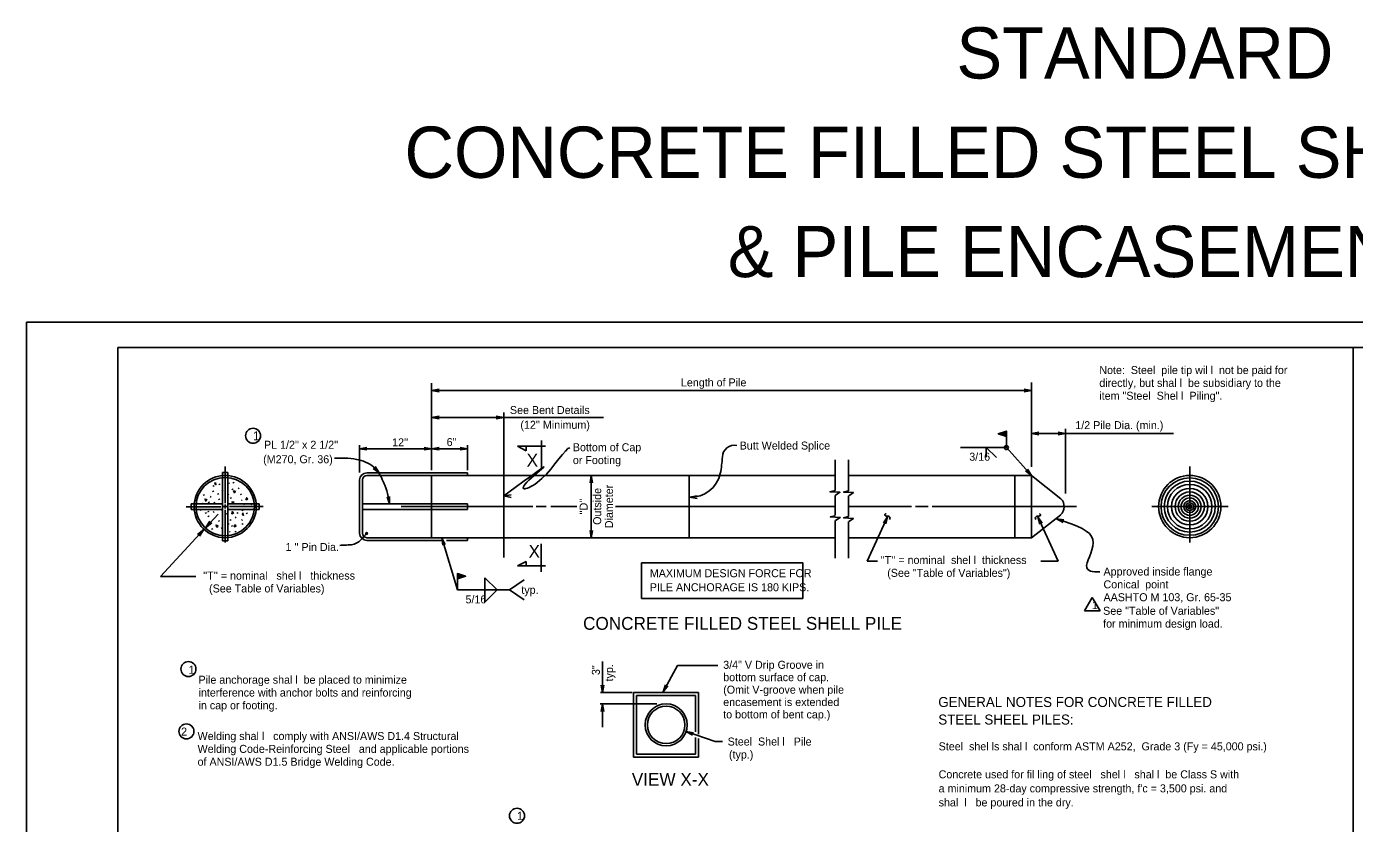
# Model space of a CAD drawing. Extents: x 1053 to 1311, y 5085 to 5337.
# Drawn here: x 1053.3 to 1163.9, y 5270.9 to 5337.3 of the extents above; entities that cross this region are included whole.
import ezdxf

# ---------------------------------------------------------------- set-up
doc = ezdxf.new("R2010")
doc.units = 0
for name, color, linetype in [('1', 7, 'Continuous'), ('2', 7, 'Continuous'), ('5', 7, 'Continuous'), ('7', 7, 'Continuous'), ('9', 7, 'Continuous'), ('B_Dimension', 7, 'Continuous'), ('B_No_Plot', 7, 'Continuous')]:
    doc.layers.add(name, color=color, linetype=linetype)

msp = doc.modelspace()

# ---------------------------------------------------------------- linework, layer by layer
at = {"layer": '1'}
for p, q in [((1060.92, 5310.54), (1229.53, 5310.54)), ((1060.92, 5200.97), (1060.92, 5310.54)), ((1087.04, 5307.57), (1087.04, 5300.32)), ((1087.04, 5306.96), (1137, 5306.96)), ((1137, 5307.62), (1137, 5300.59)), ((1093.04, 5304.71), (1087.04, 5304.71)), ((1101.34, 5304.71), (1093.04, 5304.71)), ((1134.9, 5303.58), (1134.22, 5303.36)), ((1134.9, 5303.13), (1134.22, 5303.36)), ((1134.26, 5303.34), (1134.24, 5303.36)), ((1134.25, 5303.34), (1134.29, 5303.38)), ((1134.38, 5303.3), (1134.3, 5303.38)), ((1134.31, 5303.32), (1134.4, 5303.42)), ((1134.49, 5303.27), (1134.36, 5303.4)), ((1134.37, 5303.31), (1134.52, 5303.45)), ((1134.61, 5303.23), (1134.42, 5303.42)), ((1134.43, 5303.29), (1134.63, 5303.49)), ((1134.72, 5303.19), (1134.47, 5303.44)), ((1134.49, 5303.27), (1134.75, 5303.53)), ((1134.84, 5303.15), (1134.53, 5303.46)), ((1134.55, 5303.25), (1134.86, 5303.57)), ((1134.9, 5303.17), (1134.59, 5303.48)), ((1134.61, 5303.23), (1134.9, 5303.52)), ((1134.9, 5303.25), (1134.65, 5303.5)), ((1134.66, 5303.21), (1134.9, 5303.45)), ((1134.9, 5303.32), (1134.71, 5303.52)), ((1134.72, 5303.19), (1134.9, 5303.37)), ((1134.9, 5303.4), (1134.77, 5303.53)), ((1134.9, 5303.48), (1134.83, 5303.55)), ((1134.9, 5303.56), (1134.89, 5303.57)), ((1134.9, 5302.21), (1134.9, 5303.58)), ((1139.82, 5303.39), (1137, 5303.39)), ((1139.82, 5303.77), (1139.82, 5298.38)), ((1148.83, 5303.39), (1139.82, 5303.39)), ((1081.04, 5302.4), (1081.04, 5300.12)), ((1090.04, 5302.4), (1090.04, 5300.32)), ((1096.52, 5302.31), (1094.2, 5302.31)), ((1094.92, 5302.31), (1094.92, 5301.94)), ((1096.18, 5302.79), (1096.18, 5300.47)), ((1134.9, 5302.21), (1131.08, 5302.21)), ((1133.23, 5302.21), (1133.23, 5301.41)), ((1134.07, 5301.38), (1133.23, 5302.21)), ((1134.78, 5303.17), (1134.9, 5303.29)), ((1134.84, 5303.15), (1134.9, 5303.21)), ((1134.9, 5303.13), (1134.9, 5303.14)), ((1134.9, 5302.21), (1137, 5299.88)), ((1087.04, 5302.11), (1081.04, 5302.11)), ((1090.04, 5302.11), (1087.04, 5302.11)), ((1120.65, 5301.18), (1120.65, 5298.64)), ((1121.76, 5301.18), (1121.76, 5298.61)), ((1070.08, 5300.13), (1069.62, 5300.13)), ((1069.62, 5300.13), (1069.62, 5294.45)), ((1069.85, 5300.62), (1069.85, 5297.58)), ((1070.08, 5294.45), (1070.08, 5300.13)), ((1090.04, 5300.1), (1081.64, 5300.1)), ((1090.04, 5300.1), (1090.04, 5299.88)), ((1150.17, 5300.63), (1150.17, 5297.59)), ((1068.85, 5299.04), (1068.91, 5298.97)), ((1069.34, 5299.19), (1069.39, 5299.11)), ((1070.15, 5299.28), (1070.21, 5299.21)), ((1070.52, 5299.32), (1070.57, 5299.24)), ((1081.04, 5295.07), (1081.04, 5299.51)), ((1081.27, 5295.07), (1081.27, 5299.51)), ((1087.04, 5299.88), (1081.64, 5299.88)), ((1087.04, 5294.7), (1087.04, 5299.88)), ((1087.04, 5299.88), (1120.65, 5299.88)), ((1100.33, 5299.88), (1100.33, 5294.7)), ((1108.49, 5294.7), (1108.49, 5299.88)), ((1121.76, 5299.88), (1137, 5299.88)), ((1135.6, 5294.7), (1135.6, 5299.88)), ((1137, 5294.7), (1137, 5299.88)), ((1137, 5299.88), (1139.44, 5297.95)), ((1068.05, 5298.3), (1068.1, 5298.22)), ((1068.61, 5298.14), (1068.67, 5298.07)), ((1068.82, 5298.59), (1068.87, 5298.51)), ((1069.23, 5298.37), (1069.29, 5298.3)), ((1069.33, 5297.94), (1069.38, 5297.86)), ((1069.6, 5298.69), (1069.65, 5298.61)), ((1070.08, 5298.33), (1070.13, 5298.25)), ((1070.29, 5298.04), (1070.35, 5297.96)), ((1070.42, 5298.77), (1070.48, 5298.7)), ((1070.94, 5298.85), (1071, 5298.77)), ((1071.14, 5298.35), (1071.19, 5298.27)), ((1071.2, 5297.86), (1071.26, 5297.79)), ((1108.51, 5298.07), (1109.16, 5298.19)), ((1108.51, 5298.07), (1109.16, 5297.96)), ((1120.65, 5298.21), (1120.65, 5296.57)), ((1121.76, 5298.18), (1121.76, 5296.47)), ((1066.61, 5297.28), (1069.49, 5297.28)), ((1067.01, 5297.52), (1067.01, 5297.06)), ((1067.01, 5297.52), (1069.62, 5297.52)), ((1067.01, 5297.06), (1069.62, 5297.06)), ((1067.8, 5297.05), (1067.85, 5296.97)), ((1067.97, 5297.58), (1068.03, 5297.51)), ((1068.2, 5296.79), (1068.26, 5296.71)), ((1068.42, 5296.92), (1068.47, 5296.84)), ((1068.45, 5297.69), (1068.51, 5297.61)), ((1068.86, 5296.87), (1068.92, 5296.79)), ((1068.92, 5297.66), (1068.97, 5297.58)), ((1069.57, 5297.04), (1069.62, 5296.96)), ((1069.71, 5297.29), (1070.02, 5297.29)), ((1069.85, 5297.46), (1069.85, 5297.14)), ((1069.85, 5297.02), (1069.85, 5294.3)), ((1069.96, 5296.73), (1070.01, 5296.65)), ((1070.08, 5297.52), (1072.69, 5297.52)), ((1070.08, 5297.06), (1072.69, 5297.06)), ((1070.13, 5297.08), (1070.18, 5297.01)), ((1070.21, 5297.29), (1073.01, 5297.29)), ((1070.85, 5296.79), (1070.9, 5296.71)), ((1071.27, 5297.03), (1071.32, 5296.95)), ((1071.42, 5297.52), (1071.47, 5297.44)), ((1071.63, 5296.77), (1071.68, 5296.69)), ((1072.02, 5297.53), (1072.07, 5297.45)), ((1072.69, 5297.06), (1072.69, 5297.52)), ((1081.04, 5297.4), (1081.04, 5297.17)), ((1090.04, 5297.52), (1081.27, 5297.52)), ((1090.04, 5297.06), (1081.27, 5297.06)), ((1084.5, 5297.29), (1095.46, 5297.29)), ((1090.04, 5297.52), (1090.04, 5297.06)), ((1095.74, 5297.29), (1096.59, 5297.29)), ((1096.97, 5297.29), (1099.14, 5297.29)), ((1102.36, 5297.29), (1120.65, 5297.29)), ((1121.76, 5297.29), (1126.99, 5297.29)), ((1127.33, 5297.29), (1128.39, 5297.29)), ((1128.73, 5297.29), (1140.73, 5297.29)), ((1147.01, 5297.29), (1150.17, 5297.29)), ((1150, 5297.29), (1150.33, 5297.29)), ((1150.17, 5297.46), (1150.17, 5297.14)), ((1150.17, 5297.03), (1150.17, 5294.31)), ((1150.51, 5297.29), (1153.38, 5297.29)), ((1069.27, 5296.66), (1068.22, 5295.53)), ((1068.22, 5295.53), (1068.58, 5296.09)), ((1068.22, 5295.53), (1068.75, 5295.93)), ((1068.43, 5296.53), (1068.48, 5296.45)), ((1069.31, 5296.13), (1069.36, 5296.05)), ((1070.11, 5295.87), (1070.16, 5295.79)), ((1070.27, 5296.21), (1070.33, 5296.13)), ((1070.39, 5295.71), (1070.44, 5295.63)), ((1070.69, 5296.42), (1070.75, 5296.35)), ((1071.22, 5296.22), (1071.28, 5296.14)), ((1071.27, 5295.87), (1071.32, 5295.79)), ((1120.65, 5296.14), (1120.65, 5292.99)), ((1121.76, 5296.04), (1121.76, 5292.99)), ((1125.01, 5296.44), (1123.31, 5292.74)), ((1139.43, 5296.61), (1137, 5294.7)), ((1137.52, 5296.44), (1139.22, 5292.74)), ((1068.08, 5295.38), (1064.46, 5291.48)), ((1068.08, 5295.38), (1067.55, 5294.98)), ((1068.08, 5295.38), (1067.72, 5294.83)), ((1068.73, 5295.47), (1068.79, 5295.39)), ((1069.53, 5295.54), (1069.59, 5295.47)), ((1070.2, 5295.23), (1070.25, 5295.15)), ((1070.68, 5295.24), (1070.74, 5295.17)), ((1087.04, 5294.7), (1081.64, 5294.7)), ((1087.82, 5294.47), (1081.64, 5294.47)), ((1087.04, 5294.7), (1120.65, 5294.7)), ((1090.04, 5294.47), (1088.27, 5294.47)), ((1090.04, 5294.47), (1090.04, 5294.7)), ((1121.76, 5294.7), (1137, 5294.7)), ((1069.62, 5294.45), (1070.08, 5294.45)), ((1096.17, 5291.87), (1096.17, 5294.19)), ((1096.51, 5292.35), (1094.19, 5292.35)), ((1094.91, 5292.35), (1094.91, 5292.72)), ((1123.31, 5292.74), (1124.18, 5292.74)), ((1139.22, 5292.74), (1137.77, 5292.74)), ((1064.46, 5291.48), (1067.4, 5291.48)), ((1089.18, 5290.35), (1089.18, 5291.71)), ((1089.18, 5291.71), (1089.86, 5291.49)), ((1089.18, 5291.69), (1089.19, 5291.71)), ((1089.18, 5291.61), (1089.25, 5291.69)), ((1089.18, 5291.54), (1089.31, 5291.67)), ((1089.47, 5291.36), (1089.18, 5291.66)), ((1089.18, 5291.46), (1089.37, 5291.65)), ((1089.18, 5291.38), (1089.43, 5291.63)), ((1089.18, 5291.3), (1089.49, 5291.61)), ((1089.42, 5291.34), (1089.18, 5291.58)), ((1089.36, 5291.32), (1089.18, 5291.5)), ((1089.18, 5291.27), (1089.86, 5291.49)), ((1089.3, 5291.31), (1089.18, 5291.42)), ((1089.24, 5291.29), (1089.18, 5291.35)), ((1089.18, 5291.27), (1089.18, 5291.27)), ((1089.53, 5291.38), (1089.22, 5291.7)), ((1089.24, 5291.29), (1089.55, 5291.59)), ((1089.59, 5291.4), (1089.33, 5291.66)), ((1089.36, 5291.32), (1089.61, 5291.57)), ((1089.65, 5291.42), (1089.45, 5291.62)), ((1089.47, 5291.36), (1089.66, 5291.55)), ((1089.71, 5291.44), (1089.56, 5291.59)), ((1089.59, 5291.4), (1089.72, 5291.53)), ((1089.77, 5291.46), (1089.68, 5291.55)), ((1089.7, 5291.44), (1089.78, 5291.52)), ((1089.83, 5291.48), (1089.79, 5291.51)), ((1089.82, 5291.47), (1089.84, 5291.5)), ((1091.48, 5291.37), (1092.5, 5290.35)), ((1091.48, 5290.35), (1091.48, 5291.37)), ((1089.18, 5290.35), (1092.5, 5290.35)), ((1091.48, 5290.35), (1091.48, 5289.32)), ((1091.48, 5289.32), (1092.5, 5290.35)), ((1092.5, 5290.35), (1093.53, 5290.35)), ((1141.4, 5288.6), (1142.05, 5289.73)), ((1142.7, 5288.6), (1142.05, 5289.73)), ((1141.4, 5288.6), (1142.7, 5288.6)), ((1101.28, 5281.82), (1101.28, 5284.38)), ((1101.28, 5278.93), (1101.28, 5280.84))]:
    msp.add_line(p, q, dxfattribs=at)
for points in [[(1136.38, 5307.07), (1137, 5306.96), (1136.38, 5306.85)], [(1137.61, 5303.28), (1137, 5303.39), (1137.61, 5303.5)], [(1139.2, 5303.5), (1139.82, 5303.39), (1139.2, 5303.28)], [(1081.64, 5302.01), (1081.04, 5302.11), (1081.64, 5302.22)], [(1082.33, 5300.62), (1082.66, 5300.1), (1082.18, 5300.47)], [(1069.03, 5299.31), (1068.98, 5299.21), (1069.07, 5299.11), (1069.04, 5299.31)], [(1100.23, 5299.28), (1100.33, 5299.88), (1100.44, 5299.28)], [(1068.33, 5297.83), (1068.23, 5297.75), (1068.17, 5297.92), (1068.34, 5297.86)], [(1070.72, 5298.51), (1070.62, 5298.44), (1070.55, 5298.6), (1070.73, 5298.55)], [(1071.73, 5297.95), (1071.64, 5298.03), (1071.57, 5297.86), (1071.74, 5297.92)], [(1083.54, 5298.14), (1083.53, 5297.53), (1083.33, 5298.1)], [(1120.63, 5298.63), (1120.21, 5298.53), (1121.04, 5298.48), (1120.65, 5298.21)], [(1121.76, 5298.6), (1121.35, 5298.5), (1122.17, 5298.46), (1121.78, 5298.19)], [(1070.55, 5296.79), (1070.46, 5296.87), (1070.39, 5296.7), (1070.56, 5296.76)], [(1070.59, 5297.61), (1070.49, 5297.54), (1070.42, 5297.7), (1070.6, 5297.65)], [(1071.32, 5296.76), (1071.28, 5296.66), (1071.37, 5296.56), (1071.33, 5296.76)], [(1069.25, 5295.66), (1069.16, 5295.59), (1069.09, 5295.75), (1069.26, 5295.7)], [(1070.76, 5295.7), (1070.66, 5295.77), (1070.6, 5295.61), (1070.77, 5295.66)], [(1120.64, 5296.53), (1120.23, 5296.43), (1121.06, 5296.39), (1120.66, 5296.12)], [(1121.76, 5296.46), (1121.35, 5296.35), (1122.17, 5296.31), (1121.78, 5296.04)], [(1124.66, 5295.94), (1125.01, 5296.44), (1124.85, 5295.85)], [(1139.63, 5295.98), (1139.07, 5296.26), (1139.69, 5296.19)], [(1100.44, 5295.3), (1100.33, 5294.7), (1100.23, 5295.3)], [(1101.38, 5282.43), (1101.28, 5281.82), (1101.17, 5282.43)], [(1106.7, 5282.36), (1106.31, 5281.87), (1106.51, 5282.46)], [(1101.17, 5280.22), (1101.28, 5280.84), (1101.38, 5280.22)], [(1108.77, 5278.25), (1108.23, 5278.55), (1108.84, 5278.46)]]:
    msp.add_lwpolyline(points, dxfattribs=at)
for points in [[(1134.9, 5303.13), (1134.22, 5303.36), (1134.9, 5303.58)], [(1089.18, 5291.27), (1089.86, 5291.49), (1089.18, 5291.71)]]:
    msp.add_lwpolyline(points, close=True, dxfattribs=at)
for centre, radius in [((1134.9, 5302.21), 0.167), ((1069.85, 5297.29), 2.59), ((1069.85, 5297.29), 2.43), ((1150.17, 5297.29), 2.59), ((1150.17, 5297.29), 2.39), ((1150.17, 5297.29), 2.12), ((1150.17, 5297.29), 1.85), ((1150.17, 5297.29), 1.52), ((1150.17, 5297.29), 1.22), ((1150.17, 5297.29), 0.95), ((1150.17, 5297.29), 0.728), ((1150.17, 5297.29), 0.496), ((1150.17, 5297.29), 0.325), ((1150.17, 5297.29), 0.167), ((1081.64, 5295.07), 0.0317)]:
    msp.add_circle(centre, radius, dxfattribs=at)
for centre, radius, start, end in [((1112.25, 5301.4), 1, 78.5896, 178.2489), ((1101.15, 5302.02), 10.12, 348.7897, 356.6474), ((1081.64, 5299.51), 0.596, 90, 180), ((1108.63, 5300.57), 2.5, 267.3161, 348.1785), ((1081.64, 5299.51), 0.367, 90, 180), ((1138.75, 5297.28), 0.959, 314.3367, 43.8744), ((1081.64, 5295.07), 0.596, 180, 270), ((1081.64, 5295.07), 0.367, 180, 270)]:
    msp.add_arc(centre, radius, start, end, dxfattribs=at)
for points in [[(1078.95, 5301.32), (1079.82, 5301.33), (1080.79, 5301.22), (1082.2, 5300.6), (1082.66, 5300.1)], [(1082.62, 5300.14), (1082.93, 5299.56), (1083.15, 5299.07), (1083.43, 5298.14), (1083.53, 5297.53)], [(1125.17, 5296.22), (1125.21, 5296.37), (1125.19, 5296.41), (1125.13, 5296.47), (1125.05, 5296.49), (1124.96, 5296.49), (1124.86, 5296.51), (1124.82, 5296.53), (1124.78, 5296.58), (1124.78, 5296.62), (1124.82, 5296.66), (1124.88, 5296.7)], [(1137.36, 5296.22), (1137.31, 5296.37), (1137.34, 5296.41), (1137.4, 5296.47), (1137.48, 5296.49), (1137.56, 5296.49), (1137.67, 5296.51), (1137.71, 5296.53), (1137.75, 5296.58), (1137.75, 5296.62), (1137.71, 5296.66), (1137.65, 5296.7)], [(1079.39, 5294.06), (1079.83, 5294.08), (1080.36, 5294.12), (1080.82, 5294.26), (1081.15, 5294.52), (1081.64, 5295.07)]]:
    msp.add_spline(points, degree=3, dxfattribs=at)
at = {"layer": '2'}
for p, q in [((1094.2, 5302.31), (1094.92, 5301.94)), ((1094.19, 5292.35), (1094.91, 5292.72))]:
    msp.add_line(p, q, dxfattribs=at)
at = {"layer": '5'}
for p, q in [((1107.51, 5284.06), (1106.31, 5281.87)), ((1110.88, 5284.06), (1107.51, 5284.06)), ((1103.73, 5281.82), (1101.09, 5281.82)), ((1105.79, 5280.87), (1101.08, 5280.87)), ((1110.66, 5277.72), (1108.23, 5278.55)), ((1111.26, 5277.72), (1110.66, 5277.72))]:
    msp.add_line(p, q, dxfattribs=at)
at = {"layer": '7'}
for p, q in [((1163.79, 5310.54), (1163.79, 5200.97)), ((1093.04, 5293.05), (1093.04, 5305.12)), ((1087.9, 5294.7), (1089.18, 5290.35)), ((1093.53, 5290.35), (1094.74, 5291.18)), ((1093.53, 5290.35), (1094.74, 5289.52))]:
    msp.add_line(p, q, dxfattribs=at)
msp.add_lwpolyline([(1104.53, 5292.61), (1117.94, 5292.61), (1117.94, 5289.64), (1104.53, 5289.64)], close=True, dxfattribs=at)
for centre, radius in [((1072.17, 5303.19), 0.625), ((1081.63, 5295.06), 0.0743), ((1066.79, 5283.76), 0.625), ((1106.57, 5279.11), 1.75), ((1106.57, 5279.11), 1.56), ((1066.62, 5278.57), 0.625), ((1094.15, 5271.54), 0.625)]:
    msp.add_circle(centre, radius, dxfattribs=at)
for points in [[(1098.56, 5302.19), (1098.19, 5302.19), (1096.28, 5298.93), (1093.05, 5298.19), (1098.56, 5302.19), (1093.05, 5298.19)], [(1139.07, 5296.26), (1140.93, 5295.71), (1142.92, 5294.8), (1140.99, 5291.95), (1142.09, 5291.82), (1142.68, 5291.86)]]:
    msp.add_open_spline(points, degree=3, dxfattribs=at)
at = {"layer": '9'}
for p, q in [((1109.27, 5281.82), (1103.86, 5281.82)), ((1103.86, 5281.82), (1103.86, 5276.41)), ((1104.11, 5281.57), (1104.11, 5276.66)), ((1109.02, 5281.57), (1104.11, 5281.57)), ((1109.02, 5278.52), (1109.02, 5281.57)), ((1109.27, 5278.33), (1109.27, 5281.82)), ((1109.02, 5276.66), (1109.02, 5278.05)), ((1109.27, 5276.41), (1109.27, 5277.97)), ((1103.86, 5276.41), (1109.27, 5276.41)), ((1104.11, 5276.66), (1109.02, 5276.66))]:
    msp.add_line(p, q, dxfattribs=at)
at = {"layer": 'B_Dimension'}
for points in [[(1087.66, 5306.85), (1087.04, 5306.96), (1087.66, 5307.07)], [(1087.66, 5304.61), (1087.04, 5304.71), (1087.66, 5304.82)], [(1092.42, 5304.82), (1093.04, 5304.71), (1092.42, 5304.61)], [(1086.42, 5302.22), (1087.04, 5302.11), (1086.42, 5302.01)], [(1087.66, 5302.01), (1087.04, 5302.11), (1087.66, 5302.22)], [(1089.42, 5302.22), (1090.04, 5302.11), (1089.42, 5302.01)], [(1136.67, 5300.41), (1137, 5299.88), (1136.5, 5300.26)], [(1093.66, 5298.05), (1093.05, 5298.19), (1093.67, 5298.27)], [(1137.68, 5295.83), (1137.52, 5296.44), (1137.88, 5295.92)], [(1087.97, 5294.08), (1087.9, 5294.7), (1088.17, 5294.14)]]:
    msp.add_lwpolyline(points, dxfattribs=at)
at = {"layer": 'B_No_Plot'}
msp.add_lwpolyline([(1053.31, 5312.65), (1231.97, 5312.65), (1231.97, 5198.86), (1053.31, 5198.86)], close=True, dxfattribs=at)

# ---------------------------------------------------------------- texts
at = {"layer": '1'}
for s, height, p in [('Note:  Steel  pile tip wil l  not be paid for ', 0.6667, (1142.64, 5308.33)), ('Length of Pile', 0.6667, (1107.8, 5307.3)), ('directly, but shal l  be subsidiary to the ', 0.6667, (1142.64, 5307.26)), ('item "Steel  Shel l  Piling".', 0.6667, (1142.64, 5306.19)), ("(12'' Minimum)", 0.6667, (1094.43, 5303.77)), ('1/2 Pile Dia. (min.)', 0.6667, (1140.64, 5303.74)), ("PL 1/2'' x 2 1/2''", 0.6667, (1073.08, 5302.11)), ("12''", 0.667, (1083.75, 5302.31)), ("6''", 0.667, (1088.29, 5302.33)), ('Bottom of Cap ', 0.6667, (1098.8, 5301.9)), ('Butt Welded Splice', 0.6667, (1112.69, 5302.04)), ('(M270, Gr. 36)', 0.6667, (1073.01, 5300.9)), ('or Footing', 0.667, (1098.8, 5300.83)), ('3/16', 0.667, (1131.81, 5301.11)), ("1 '' Pin Dia.", 0.6667, (1074.87, 5293.59)), ("''T'' = nominal  shel l  thickness", 0.6667, (1124.43, 5292.51)), ("''T'' = nominal   shel l   thickness ", 0.6667, (1068.01, 5291.21)), ('MAXIMUM DESIGN FORCE FOR', 0.6667, (1105.21, 5291.41)), ('(See "Table of Variables")', 0.6667, (1124.98, 5291.44)), ('Approved inside flange', 0.6667, (1142.99, 5291.55)), ('Conical  point', 0.6667, (1142.99, 5290.48)), ('  (See Table of Variables)', 0.6667, (1068.01, 5290.14)), ('typ.', 0.667, (1094.51, 5290.02)), ('PILE ANCHORAGE IS 180 KIPS.', 0.6667, (1105.21, 5290.24)), ('AASHTO M 103, Gr. 65-35', 0.6667, (1142.99, 5289.41)), ('5/16', 0.667, (1089.86, 5289.23)), ('1', 0.667, (1142.03, 5288.75)), ('See "Table of Variables"', 0.6667, (1142.96, 5288.28)), ('for minimum design load.', 0.6667, (1142.96, 5287.21)), ('1', 0.665, (1066.8, 5283.37)), ('Pile anchorage shal l  be placed to minimize', 0.665, (1067.63, 5282.54)), ('interference with anchor bolts and reinforcing', 0.665, (1067.63, 5281.47)), ('in cap or footing.', 0.665, (1067.63, 5280.41)), (' 2', 0.667, (1065.93, 5278.22)), ('Welding shal l   comply with ANSI/AWS D1.4 Structural  ', 0.6667, (1067.55, 5277.85)), ('Welding Code-Reinforcing Steel   and applicable portions ', 0.6667, (1067.55, 5276.78)), ('Steel  shel ls shal l  conform ASTM A252,  Grade 3 (Fy = 45,000 psi.)', 0.6667, (1129.26, 5276.99)), ('of ANSI/AWS D1.5 Bridge Welding Code.', 0.6667, (1067.55, 5275.71)), ('Concrete used for fil ling of steel   shel l   shal l  be Class S with', 0.6667, (1129.26, 5274.66)), ("a minimum 28-day compressive strength, f'c = 3,500 psi. and ", 0.6667, (1129.26, 5273.49)), ('shal  l   be poured in the dry.', 0.6667, (1129.26, 5272.32)), ('1', 0.665, (1094.16, 5271.21))]:
    msp.add_text(s, height=height, dxfattribs=at).set_placement(p)
for s, p in [('Diameter', (1102.14, 5295.49)), ("''D''", (1100.03, 5296.63)), ('Outside', (1101.16, 5295.77))]:
    msp.add_text(s, height=0.667, rotation=90, dxfattribs=at).set_placement(p)
at = {"layer": '7'}
for s, height, p in [('STANDARD', 4.268, (1130.74, 5332.94)), ('CONCRETE FILLED STEEL SHELL PILES ', 4.268, (1084.78, 5324.67)), ('& PILE ENCASEMENTS', 4.268, (1111.7, 5316.4)), ('See Bent Details', 0.6667, (1093.56, 5305)), ('1', 0.733, (1072.16, 5302.82)), ('CONCRETE FILLED STEEL SHELL PILE', 1.067, (1099.65, 5287.03)), ('3/4" V Drip Groove in ', 0.6667, (1111.32, 5283.78)), ('bottom surface of cap.', 0.6667, (1111.32, 5282.75)), ('(Omit V-groove when pile', 0.6667, (1111.32, 5281.71)), ('encasement is extended', 0.6667, (1111.32, 5280.68)), ('GENERAL NOTES FOR CONCRETE FILLED', 0.8333, (1129.23, 5280.6)), ('to bottom of bent cap.)', 0.6667, (1111.32, 5279.65)), ('STEEL SHEEL PILES:', 0.8333, (1129.23, 5279.14)), ('Steel  Shel l   Pile', 0.6667, (1111.69, 5277.39)), ('(typ.)', 0.667, (1111.8, 5276.31))]:
    msp.add_text(s, height=height, dxfattribs=at).set_placement(p)
for s, height, rotation, p in [('X', 1.07, 360, (1094.95, 5300.62)), ('X', 1.07, 360, (1095.11, 5293.03)), ('3"', 0.667, 90, (1101.05, 5283.26)), ('typ.', 0.667, 90, (1102.15, 5282.73))]:
    msp.add_text(s, height=height, rotation=rotation, dxfattribs=at).set_placement(p)
at = {"layer": '9'}
msp.add_text('VIEW X-X', height=1.067, dxfattribs=at).set_placement((1103.71, 5274.04))

doc.saveas('drawing.dxf')
